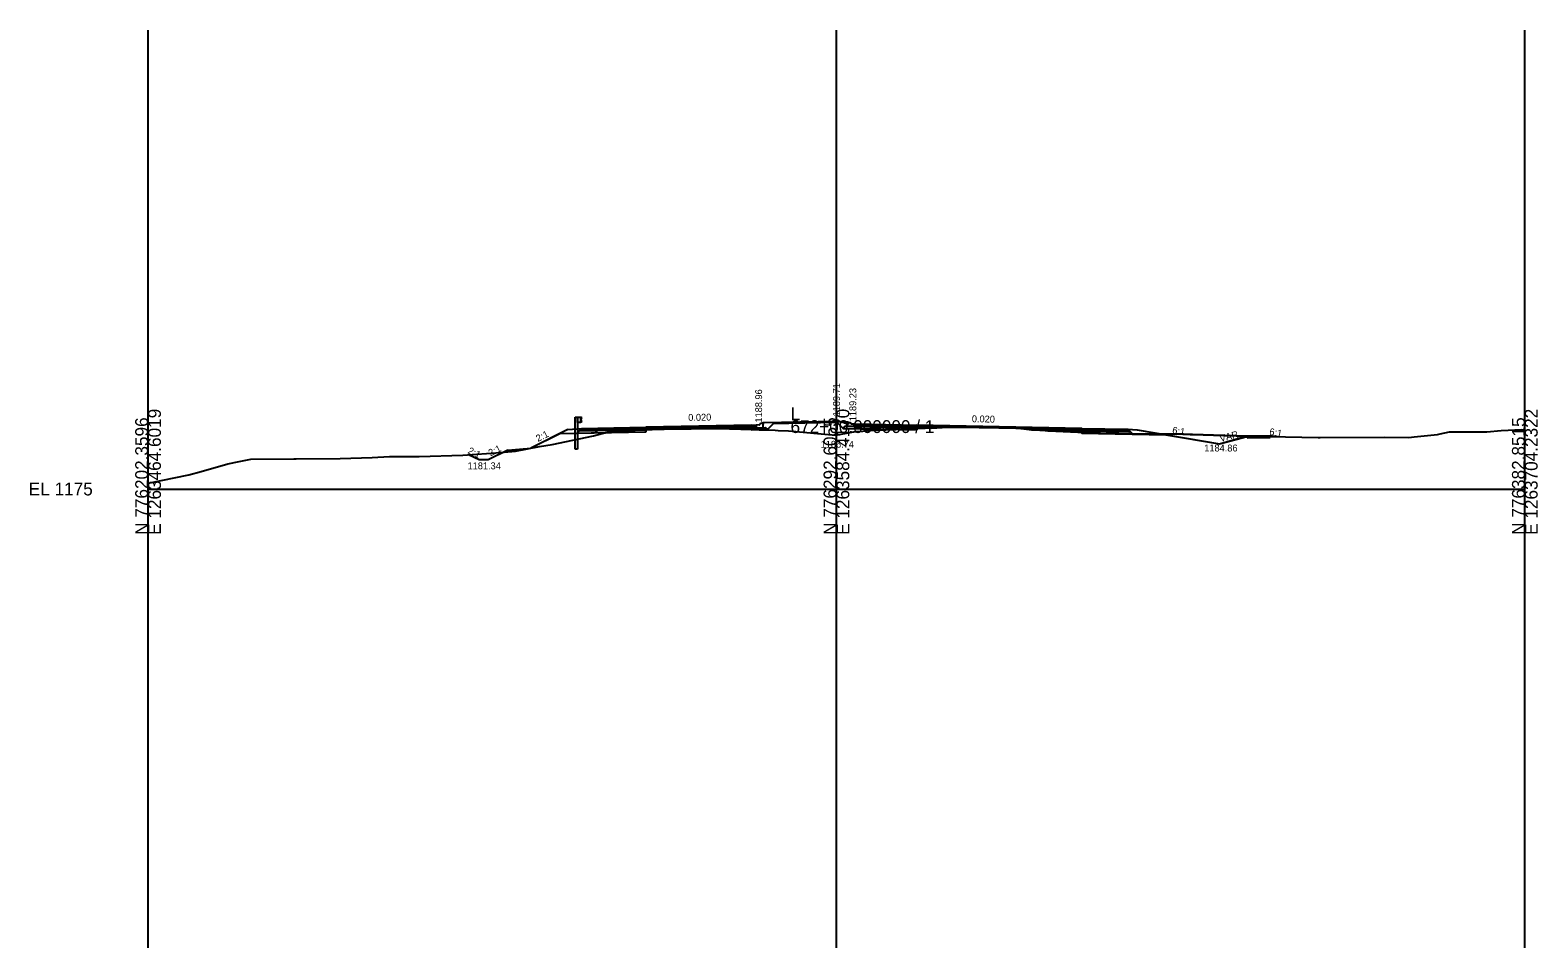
# Model space of a CAD drawing. Extents: x -41 to 1262860, y -100 to 777489.
# Drawn here: x -25.7 to 302.8, y 4310 to 4510 of the extents above; entities that cross this region are included whole.
import ezdxf

# ---------------------------------------------------------------- set-up
doc = ezdxf.new("R2010")
doc.units = 0
for name, color, linetype in [('Exist Cross Section Cell', 7, 'Continuous'), ('Exist XS Center Line Elevation Label', 7, 'Continuous'), ('Exist XS Ground Line', 7, 'Continuous'), ('Prop CMT Guardrail Graphics', 7, 'Continuous'), ('Prop CMT Pvmt Concrete', 7, 'Continuous'), ('Prop CMT Pvmt Course 1', 7, 'Continuous'), ('Prop CMT Pvmt Course 4', 7, 'Continuous'), ('Prop CMT Pvmt Surface', 7, 'Continuous'), ('Prop CMT Shld Paved Course 1', 7, 'Continuous'), ('Prop CMT Shld Paved Course 2', 7, 'Continuous'), ('Prop CMT Shld Paved Course 4', 7, 'Continuous'), ('Prop CMT Subgrade Earthwork', 7, 'Continuous'), ('Prop Conc Curb and Gutter', 7, 'Continuous'), ('Prop Conc Island Cover', 7, 'Continuous'), ('Prop XS Ditch Standard Text', 7, 'Continuous'), ('Prop XS Earthwork Shape', 7, 'Continuous'), ('Prop XS Elevation Labels', 7, 'Continuous'), ('Prop XS Exc Vertical Line 1', 7, 'Continuous'), ('Prop XS Exc Vertical Line 2', 7, 'Continuous'), ('Prop XS Exc Vertical Line 3', 7, 'Continuous'), ('Prop XS Finish Grade', 7, 'Continuous'), ('Prop XS Hydro Elevations', 7, 'Continuous'), ('Prop XS SE Text', 7, 'Continuous'), ('Prop XS Side Slope Text', 7, 'Continuous'), ('Scratch_Level_0', 7, 'Continuous'), ('Scratch_Level_1', 7, 'Continuous'), ('Scratch_Level_4', 7, 'Continuous'), ('Scratch_Level_6', 7, 'Continuous')]:
    doc.layers.add(name, color=color, linetype=linetype)

msp = doc.modelspace()

# ---------------------------------------------------------------- linework, layer by layer
at = {"layer": 'Exist Cross Section Cell'}
for p, q in [((150, 4410), (150, 4425)), ((0, 4410), (150, 4410)), ((150, 4410), (300, 4410))]:
    msp.add_line(p, q, dxfattribs=at)
at = {"layer": 'Exist XS Ground Line'}
msp.add_lwpolyline([(0, 4411.27), (8.92, 4413.11), (11.54, 4413.78), (17.4, 4415.47), (19.82, 4415.96), (22.37, 4416.52), (31.76, 4416.55), (32.3, 4416.55), (41.83, 4416.65), (48.86, 4416.9), (52.58, 4417.08), (59.09, 4417.1), (68.59, 4417.37), (76.79, 4417.98), (80.04, 4418.25), (85.29, 4419.27), (88.06, 4419.73), (97.04, 4421.59), (100.07, 4422.36), (101.38, 4422.56), (107.37, 4422.86), (108.07, 4422.86), (111.65, 4423.02), (111.84, 4423.03), (112.46, 4423.05), (124.32, 4423.2), (126.69, 4423.12), (136.65, 4422.8), (137.3, 4422.77), (139.59, 4422.65), (149.04, 4421.79), (149.88, 4421.72), (150.23, 4421.78), (154.16, 4422.51), (155.74, 4422.62), (156.16, 4422.66), (158.62, 4422.79), (165.73, 4423.12), (173.07, 4423.38), (177.73, 4423.53), (181.07, 4423.46), (189.58, 4423.27), (191.45, 4423.06), (192.5, 4422.91), (194.87, 4422.79), (196.05, 4422.71), (197.83, 4422.61), (208.91, 4422.12), (211.23, 4422.01), (211.39, 4422.02), (213.75, 4422.06), (213.83, 4422.06), (225.59, 4421.93), (227.06, 4421.89), (227.34, 4421.9), (227.59, 4421.91), (234.47, 4421.65), (237.12, 4421.61), (254.99, 4421.25), (255.15, 4421.25), (255.21, 4421.25), (255.27, 4421.25), (255.4, 4421.25), (269.38, 4421.33), (274.64, 4421.22), (275.3, 4421.28), (275.9, 4421.35), (280.96, 4421.89), (281.59, 4422.01), (283.6, 4422.44), (289.54, 4422.46), (291.74, 4422.49), (294.83, 4422.73), (299.32, 4422.94), (300, 4422.88)], dxfattribs=at)
at = {"layer": 'Prop CMT Guardrail Graphics'}
for p, q in [((93.1, 4425.69), (93.59, 4425.69)), ((93.1, 4423.19), (93.1, 4425.69)), ((93.59, 4424.51), (93.59, 4425.69)), ((93.59, 4425.69), (94.26, 4425.69)), ((93.59, 4425.69), (93.59, 4423.18)), ((94.26, 4425.69), (94.26, 4424.51)), ((94.26, 4425.61), (94.26, 4424.59)), ((94.36, 4425.59), (94.26, 4425.61)), ((94.27, 4425.15), (94.5, 4425.35)), ((94.5, 4425.49), (94.36, 4425.59)), ((94.5, 4425.35), (94.5, 4425.49)), ((93.1, 4418.68), (93.1, 4423.19)), ((94.26, 4424.51), (93.59, 4424.51)), ((93.59, 4423.18), (93.59, 4418.68)), ((94.26, 4424.59), (94.36, 4424.61)), ((94.27, 4425.06), (94.27, 4425.15)), ((94.5, 4424.85), (94.27, 4425.06)), ((94.36, 4424.61), (94.5, 4424.71)), ((94.5, 4424.71), (94.5, 4424.85)), ((93.59, 4418.68), (93.1, 4418.68))]:
    msp.add_line(p, q, dxfattribs=at)
at = {"layer": 'Prop CMT Pvmt Concrete'}
for p, q in [((239.5, 4421.47), (244.5, 4421.57)), ((239.5, 4421.47), (239.5, 4421.14)), ((239.5, 4421.14), (244.51, 4421.24)), ((244.5, 4421.57), (244.5, 4421.24))]:
    msp.add_line(p, q, dxfattribs=at)
at = {"layer": 'Prop CMT Pvmt Course 1'}
for p, q in [((131.5, 4423.67), (132.5, 4423.69)), ((132.5, 4423.69), (132.5, 4423.94)), ((153.89, 4424.21), (153.89, 4423.96)), ((153.89, 4423.96), (167.49, 4423.69))]:
    msp.add_line(p, q, dxfattribs=at)
for points in [[(108.5, 4423.46), (108.5, 4423.21), (131.5, 4423.67), (131.5, 4423.67), (131.5, 4423.92), (131.5, 4423.92), (131.5, 4423.92), (108.5, 4423.46), (108.5, 4423.46)], [(203.5, 4423.22), (203.5, 4423.22), (167.5, 4423.94), (167.5, 4423.94), (167.5, 4423.94), (167.5, 4423.69), (167.5, 4423.69), (203.5, 4422.97), (203.5, 4423.22)]]:
    msp.add_lwpolyline(points, dxfattribs=at)
at = {"layer": 'Prop CMT Pvmt Course 4'}
for p in [(93.9, 4422.59), (108.5, 4422.42)]:
    msp.add_line(p, (93.44, 4422.12), dxfattribs=at)
at = {"layer": 'Prop CMT Pvmt Surface'}
for p, q in [((94.5, 4423.18), (108.5, 4423.46)), ((108.5, 4423.46), (131.5, 4423.92)), ((131.5, 4423.92), (132.5, 4423.94)), ((153.89, 4424.21), (167.5, 4423.94)), ((203.5, 4423.22), (167.5, 4423.94)), ((203.5, 4423.22), (213.5, 4423.02))]:
    msp.add_line(p, q, dxfattribs=at)
at = {"layer": 'Prop CMT Shld Paved Course 1'}
for p, q in [((108.5, 4423.21), (94.24, 4422.93)), ((94.5, 4423.18), (94.24, 4422.93)), ((104.5, 4423.38), (104.5, 4423.38)), ((108.5, 4423.46), (108.5, 4423.21)), ((108.5, 4423.21), (108.5, 4423.21)), ((203.5, 4423.22), (203.5, 4422.97)), ((203.5, 4422.97), (203.5, 4422.97)), ((203.5, 4422.97), (213.76, 4422.77)), ((207.5, 4423.14), (207.5, 4423.14)), ((213.76, 4422.77), (213.5, 4423.02))]:
    msp.add_line(p, q, dxfattribs=at)
at = {"layer": 'Prop CMT Shld Paved Course 2'}
for p, q in [((93.9, 4422.59), (94.24, 4422.93)), ((108.5, 4422.88), (93.9, 4422.59)), ((103.9, 4422.79), (103.9, 4422.79)), ((103.9, 4422.79), (103.9, 4422.79)), ((108.5, 4423.21), (111.65, 4423.27)), ((108.5, 4423.21), (108.5, 4422.88)), ((108.5, 4422.88), (108.5, 4423.21)), ((108.5, 4423.21), (108.5, 4423.21)), ((108.5, 4423.21), (108.5, 4423.21)), ((111.65, 4423.02), (108.5, 4422.88)), ((108.5, 4422.88), (108.5, 4422.88)), ((108.5, 4422.88), (108.5, 4422.88)), ((111.65, 4423.27), (111.84, 4423.28)), ((111.65, 4423.27), (111.65, 4423.27)), ((111.84, 4423.03), (111.65, 4423.02)), ((111.65, 4423.02), (111.65, 4423.02)), ((111.65, 4423.02), (111.65, 4423.02)), ((111.84, 4423.28), (112.46, 4423.29)), ((112.46, 4423.05), (111.84, 4423.03)), ((112.46, 4423.29), (124.32, 4423.53)), ((112.46, 4423.29), (112.46, 4423.29)), ((124.32, 4423.2), (112.46, 4423.05)), ((112.46, 4423.05), (112.46, 4423.05)), ((124.32, 4423.53), (126.69, 4423.58)), ((124.32, 4423.53), (124.32, 4423.53)), ((124.51, 4423.2), (124.32, 4423.2)), ((124.32, 4423.2), (124.32, 4423.2)), ((124.32, 4423.2), (124.32, 4423.2)), ((126.69, 4423.24), (124.51, 4423.2)), ((126.69, 4423.58), (131.5, 4423.67)), ((126.69, 4423.58), (126.69, 4423.58)), ((131.5, 4423.34), (126.69, 4423.24)), ((126.69, 4423.24), (126.69, 4423.24)), ((131.5, 4423.67), (131.5, 4423.67)), ((131.5, 4423.67), (131.5, 4423.67)), ((131.5, 4423.67), (131.5, 4423.34)), ((131.5, 4423.34), (131.5, 4423.34)), ((131.51, 4423.34), (132.5, 4423.36)), ((132.5, 4423.69), (132.5, 4423.36)), ((153.89, 4423.63), (153.89, 4423.96)), ((153.89, 4423.63), (167.5, 4423.36)), ((173.07, 4423.58), (167.5, 4423.69)), ((167.5, 4423.69), (167.5, 4423.69)), ((167.5, 4423.69), (167.5, 4423.69)), ((167.5, 4423.69), (167.5, 4423.36)), ((167.5, 4423.36), (167.5, 4423.36)), ((167.5, 4423.36), (170.68, 4423.29)), ((170.68, 4423.29), (173.07, 4423.38)), ((170.68, 4423.29), (170.68, 4423.29)), ((177.73, 4423.49), (173.07, 4423.58)), ((173.07, 4423.58), (173.07, 4423.58)), ((173.07, 4423.38), (176.95, 4423.5)), ((173.07, 4423.38), (173.07, 4423.38)), ((176.95, 4423.5), (177.73, 4423.49)), ((181.07, 4423.42), (177.73, 4423.49)), ((177.73, 4423.49), (177.73, 4423.49)), ((177.73, 4423.49), (181.07, 4423.42)), ((189.58, 4423.25), (181.07, 4423.42)), ((181.07, 4423.42), (181.07, 4423.42)), ((181.07, 4423.42), (181.07, 4423.42)), ((181.07, 4423.42), (189.58, 4423.25)), ((191.45, 4423.21), (189.58, 4423.25)), ((189.58, 4423.25), (189.58, 4423.25)), ((189.58, 4423.25), (189.58, 4423.25)), ((189.58, 4423.25), (189.83, 4423.24)), ((189.83, 4423.24), (189.83, 4423.24)), ((189.83, 4423.24), (191.45, 4423.06)), ((192.5, 4423.19), (191.45, 4423.21)), ((191.45, 4423.21), (191.45, 4423.21)), ((191.45, 4423.06), (191.45, 4423.06)), ((191.45, 4423.06), (192.5, 4422.91)), ((194.87, 4423.14), (192.5, 4423.19)), ((192.5, 4423.19), (192.5, 4423.19)), ((192.5, 4423.19), (192.5, 4423.19)), ((192.5, 4422.91), (192.5, 4422.91)), ((192.5, 4422.91), (192.5, 4422.91)), ((192.5, 4422.91), (194.3, 4422.82)), ((194.3, 4422.82), (194.3, 4422.82)), ((194.3, 4422.82), (194.3, 4422.82)), ((194.3, 4422.82), (194.3, 4422.82)), ((194.3, 4422.82), (194.87, 4422.81)), ((196.05, 4423.12), (194.87, 4423.14)), ((194.87, 4423.14), (194.87, 4423.14)), ((194.87, 4423.14), (194.87, 4423.14)), ((194.87, 4422.81), (196.05, 4422.79)), ((197.83, 4423.08), (196.05, 4423.12)), ((196.05, 4423.12), (196.05, 4423.12)), ((196.05, 4422.79), (196.05, 4422.79)), ((196.05, 4422.79), (197.83, 4422.75)), ((203.5, 4422.97), (197.83, 4423.08)), ((197.83, 4423.08), (197.83, 4423.08)), ((197.83, 4422.75), (197.83, 4422.75)), ((197.83, 4422.75), (203.5, 4422.64)), ((203.5, 4422.97), (203.5, 4422.64)), ((203.5, 4422.64), (203.5, 4422.97)), ((203.5, 4422.97), (203.5, 4422.97)), ((203.5, 4422.64), (203.5, 4422.64)), ((203.5, 4422.64), (214.1, 4422.43)), ((214.1, 4422.43), (213.76, 4422.77))]:
    msp.add_line(p, q, dxfattribs=at)
at = {"layer": 'Prop CMT Shld Paved Course 4'}
for p, q in [((97.4, 4422.66), (97.9, 4422.67)), ((103.9, 4422.79), (103.9, 4422.79)), ((108.5, 4422.88), (108.5, 4422.42)), ((124.51, 4423.2), (126.69, 4423.12)), ((131.5, 4422.97), (126.69, 4423.12)), ((131.5, 4422.88), (131.5, 4423.34)), ((131.5, 4422.88), (134.95, 4422.95)), ((132.5, 4423.36), (134.5, 4423.4)), ((134.5, 4423.4), (134.95, 4422.95)), ((151.89, 4423.67), (151.44, 4423.22)), ((151.44, 4423.22), (167.5, 4422.9)), ((153.89, 4423.63), (151.89, 4423.67)), ((167.5, 4422.9), (167.5, 4423.36)), ((170.68, 4423.29), (167.5, 4423.18)), ((194.3, 4422.82), (194.87, 4422.79)), ((194.87, 4422.79), (196.05, 4422.71)), ((197.83, 4422.61), (196.05, 4422.71)), ((203.5, 4422.36), (197.83, 4422.61)), ((203.5, 4422.64), (203.5, 4422.18)), ((203.5, 4422.18), (214.56, 4421.96)), ((214.56, 4421.96), (214.1, 4422.43))]:
    msp.add_line(p, q, dxfattribs=at)
at = {"layer": 'Prop CMT Subgrade Earthwork'}
for p, q in [((108.5, 4422.42), (89.7, 4422.04)), ((108.5, 4422.42), (108.5, 4422.88)), ((131.5, 4422.88), (131.5, 4422.97)), ((134.95, 4422.95), (131.5, 4422.88)), ((134.95, 4422.95), (136.44, 4424.44)), ((151.44, 4423.22), (149.96, 4424.71)), ((167.5, 4422.9), (151.44, 4423.22)), ((167.5, 4422.9), (167.5, 4423.18)), ((203.5, 4422.36), (203.5, 4422.18)), ((203.5, 4422.18), (221.78, 4421.81))]:
    msp.add_line(p, q, dxfattribs=at)
at = {"layer": 'Prop Conc Curb and Gutter'}
for p, q in [((133.19, 4423.96), (132.5, 4423.94)), ((132.5, 4423.94), (132.5, 4423.36)), ((132.5, 4423.36), (134, 4423.39)), ((133.25, 4424.03), (133.25, 4424.02)), ((134, 4424.39), (133.35, 4424.17)), ((134, 4423.39), (134, 4424.39)), ((134, 4423.39), (134, 4423.39)), ((152.39, 4424.66), (153.04, 4424.44)), ((152.39, 4423.66), (152.39, 4424.66)), ((153.89, 4423.63), (152.39, 4423.66)), ((153.14, 4424.31), (153.14, 4424.29)), ((153.2, 4424.23), (153.89, 4424.21)), ((153.89, 4423.63), (153.89, 4424.21))]:
    msp.add_line(p, q, dxfattribs=at)
for centre, radius, start, end in [((133.19, 4424.02), 0.0625, 271.1458, 360), ((133.4, 4424.03), 0.146, 108.435, 180), ((153, 4424.31), 0.146, 0, 71.565), ((153.21, 4424.29), 0.0625, 180, 268.8542)]:
    msp.add_arc(centre, radius, start, end, dxfattribs=at)
at = {"layer": 'Prop Conc Island Cover'}
for p, q in [((150, 4424.71), (134, 4424.39)), ((134, 4424.12), (134, 4424.12)), ((150, 4424.71), (152.39, 4424.66))]:
    msp.add_line(p, q, dxfattribs=at)
at = {"layer": 'Prop XS Earthwork Shape'}
for points in [[(93.44, 4422.12), (89.7, 4422.04), (83.43, 4418.91), (85.29, 4419.27), (88.06, 4419.73), (97.04, 4421.59), (99.6, 4422.24)], [(108.5, 4422.42), (99.6, 4422.24), (100.07, 4422.36), (101.38, 4422.56), (107.37, 4422.86), (108.07, 4422.86), (108.5, 4422.88)], [(131.5, 4422.97), (133.15, 4422.91), (131.5, 4422.88)], [(149.04, 4421.79), (149.88, 4421.72), (150.23, 4421.78), (154.16, 4422.51), (155.74, 4422.62), (156.16, 4422.66), (158.62, 4422.79), (162.93, 4422.99), (151.44, 4423.22), (150.21, 4424.45), (150, 4424.46), (136.18, 4424.18), (134.95, 4422.95), (133.15, 4422.91), (136.65, 4422.8), (137.3, 4422.77), (139.59, 4422.65)], [(167.5, 4422.9), (162.93, 4422.99), (165.73, 4423.12), (167.5, 4423.18)], [(208.91, 4422.12), (210.73, 4422.03), (203.5, 4422.18), (203.5, 4422.36)], [(213.83, 4422.06), (214.47, 4422.05), (214.56, 4421.96), (211.56, 4422.02), (213.75, 4422.06)], [(220.79, 4421.98), (221.78, 4421.81), (214.56, 4421.96), (214.47, 4422.05)], [(211.39, 4422.02), (211.56, 4422.02), (210.73, 4422.03), (211.23, 4422.01)], [(220.79, 4421.98), (221.78, 4421.81), (233.5, 4419.86), (239.5, 4421.47), (241.72, 4421.52), (237.12, 4421.61), (234.47, 4421.65), (227.59, 4421.91), (227.34, 4421.9), (227.06, 4421.89), (225.59, 4421.93)], [(245, 4421.58), (245.89, 4421.43), (241.72, 4421.52), (244.5, 4421.57)]]:
    msp.add_lwpolyline(points, close=True, dxfattribs=at)
at = {"layer": 'Prop XS Exc Vertical Line 1'}
msp.add_line((0, 4310), (0, 4510), dxfattribs=at)
at = {"layer": 'Prop XS Exc Vertical Line 2'}
msp.add_line((150, 4310), (150, 4510), dxfattribs=at)
at = {"layer": 'Prop XS Exc Vertical Line 3'}
msp.add_line((300, 4310), (300, 4510), dxfattribs=at)
at = {"layer": 'Prop XS Finish Grade'}
for p, q in [((91.5, 4422.94), (83.43, 4418.91)), ((91.5, 4422.94), (94.5, 4423.18)), ((94.5, 4423.18), (93.44, 4422.12)), ((213.5, 4423.02), (215.5, 4422.86)), ((213.5, 4423.02), (214.56, 4421.96)), ((215.5, 4422.86), (233.5, 4419.86)), ((78.43, 4418.49), (83.43, 4418.91)), ((233.5, 4419.86), (239, 4421.46)), ((244.5, 4421.57), (239, 4421.46)), ((244.5, 4421.57), (245, 4421.58)), ((245, 4421.58), (245.89, 4421.43)), ((72.12, 4416.33), (69.86, 4417.46)), ((74.12, 4416.33), (72.12, 4416.33)), ((78.43, 4418.49), (74.12, 4416.33))]:
    msp.add_line(p, q, dxfattribs=at)
at = {"layer": 'Scratch_Level_0'}
for p, q in [((134, 4424.39), (134, 4424.14)), ((152.39, 4424.66), (152.39, 4424.41))]:
    msp.add_line(p, q, dxfattribs=at)
at = {"layer": 'Scratch_Level_1'}
msp.add_line((239.5, 4421.47), (244.5, 4421.57), dxfattribs=at)
at = {"layer": 'Scratch_Level_4'}
msp.add_line((300, 4310), (300, 4510), dxfattribs=at)
at = {"layer": 'Scratch_Level_6'}
msp.add_line((0, 4310), (0, 4510), dxfattribs=at)

# ---------------------------------------------------------------- texts
at = {"layer": 'Exist Cross Section Cell'}
for s, p in [('N 776202.3596', (0, 4400)), ('E 1263464.6019', (2.8, 4400)), ('N 776292.6055', (150, 4400)), ('E 1263584.4170', (152.8, 4400)), ('N 776382.8515', (300, 4400)), ('E 1263704.2322', (302.8, 4400))]:
    msp.add_text(s, height=2.8, rotation=90, dxfattribs=at).set_placement(p)
for s, p in [('L', (140, 4425)), ('672+00.000000 / 1', (140, 4422.2)), ('EL 1175', (-26, 4408.6))]:
    msp.add_text(s, height=2.8, dxfattribs=at).set_placement(p)
at = {"layer": 'Exist XS Center Line Elevation Label'}
msp.add_text('1186.74', height=1.5, dxfattribs=at).set_placement((146.56, 4418.99))
at = {"layer": 'Prop XS Ditch Standard Text'}
for s, p in [('1184.86', (230.15, 4418.18)), ('1181.34', (69.62, 4414.3))]:
    msp.add_text(s, height=1.5, dxfattribs=at).set_placement(p)
at = {"layer": 'Prop XS Elevation Labels'}
for s, p in [('1189.23', (154.32, 4424.76)), ('1188.96', (133.8, 4424.48))]:
    msp.add_text(s, height=1.5, rotation=90, dxfattribs=at).set_placement(p)
at = {"layer": 'Prop XS Hydro Elevations'}
msp.add_text('1189.71', height=1.5, rotation=90, dxfattribs=at).set_placement((150.76, 4425.81))
at = {"layer": 'Prop XS SE Text'}
for rotation, p in [(1.1458, (117.72, 4424.83)), (358.8542, (179.5, 4424.56))]:
    msp.add_text('0.020', height=1.5, rotation=rotation, dxfattribs=at).set_placement(p)
at = {"layer": 'Prop XS Side Slope Text'}
for s, rotation, p in [('2:1', 26.5651, (84.97, 4420.23)), ('6:1', 350.5377, (223.09, 4422.13)), ('VAR.', 14.2871, (233.71, 4420.24)), ('6:1', 349.7978, (244.24, 4421.82)), ('2:1', 333.6935, (69.53, 4417.87)), ('2:1', 26.5651, (74.62, 4417.09))]:
    msp.add_text(s, height=1.5, rotation=rotation, dxfattribs=at).set_placement(p)

doc.saveas('drawing.dxf')
